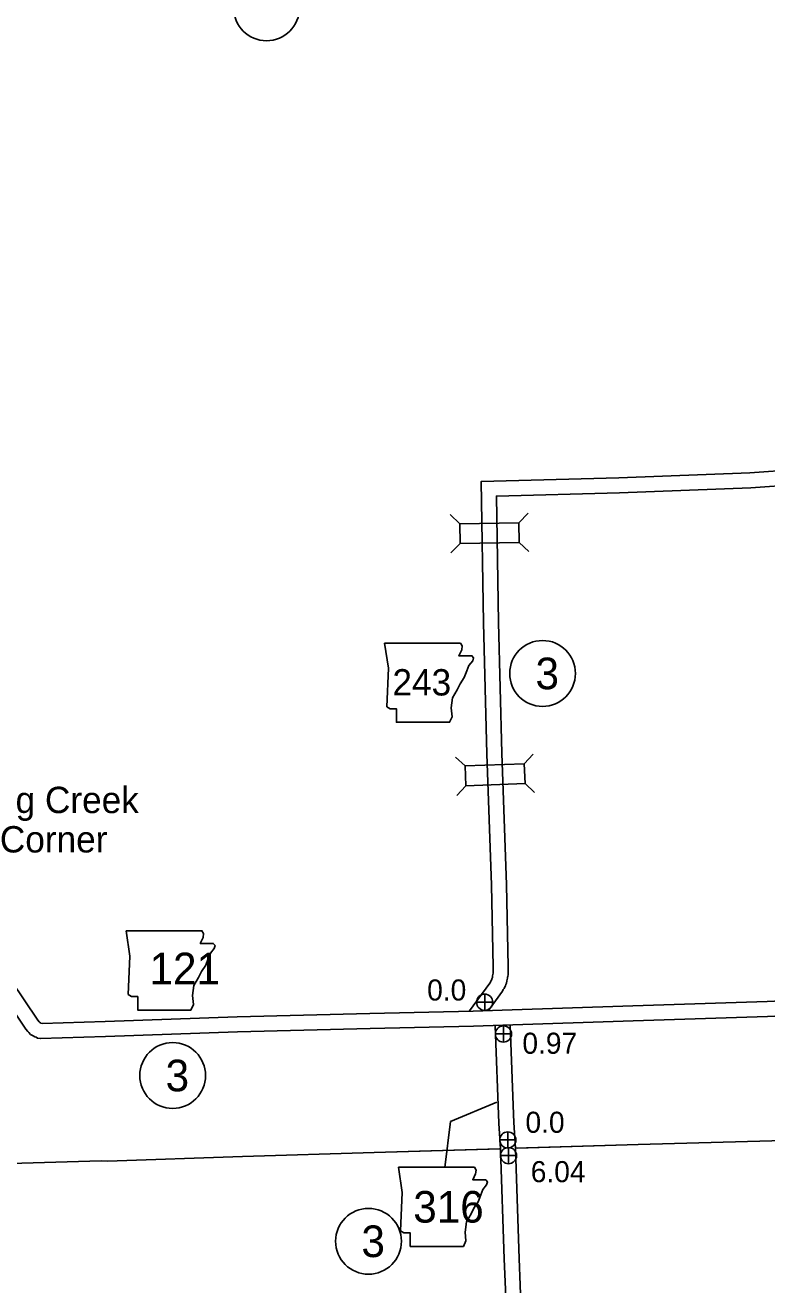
# Model space of a CAD drawing. Extents: x -939622 to -934222, y 1383701 to 1385301.
# Drawn here: x -935826.6 to -935782, y 1384106.1 to 1384181.9 of the extents above; entities that cross this region are included whole.
import ezdxf

# ---------------------------------------------------------------- set-up
doc = ezdxf.new("R2010")
doc.units = 0
for name, color, linetype in [('Level 10', 7, 'Continuous'), ('Level 2', 7, 'Continuous'), ('Level 20', 7, 'Continuous'), ('Level 21', 7, 'Continuous'), ('Level 24', 7, 'Continuous'), ('Level 25', 7, 'Continuous'), ('Level 26', 7, 'Continuous'), ('Level 27', 7, 'Continuous')]:
    doc.layers.add(name, color=color, linetype=linetype)

msp = doc.modelspace()

# ---------------------------------------------------------------- linework, layer by layer
at = {"layer": 'Level 10'}
for points in [[(-935799.877, 1384122.563), (-935798.668, 1384124.24), (-935798.613, 1384124.338), (-935798.595, 1384124.364), (-935798.581, 1384124.395), (-935798.553, 1384124.45), (-935798.536, 1384124.494), (-935798.519, 1384124.533), (-935798.508, 1384124.576), (-935798.502, 1384124.606), (-935798.494, 1384124.669), (-935798.476, 1384124.765), (-935798.462, 1384124.837), (-935798.456, 1384124.863), (-935798.454, 1384124.93), (-935798.464, 1384125.208), (-935798.565, 1384130.123), (-935798.844, 1384138.033), (-935799.044, 1384145.919), (-935799.186, 1384154.404), (-935790.894, 1384154.638), (-935783.01, 1384154.93), (-935780.19, 1384155.135)], [(-935798.743, 1384122.596), (-935797.908, 1384123.755), (-935797.852, 1384123.855), (-935797.809, 1384123.916), (-935797.768, 1384124.008), (-935797.73, 1384124.082), (-935797.704, 1384124.148), (-935797.662, 1384124.245), (-935797.632, 1384124.372), (-935797.614, 1384124.452), (-935797.604, 1384124.534), (-935797.592, 1384124.596), (-935797.583, 1384124.645), (-935797.558, 1384124.747), (-935797.554, 1384124.934), (-935797.564, 1384125.233), (-935797.665, 1384130.148), (-935797.944, 1384138.06), (-935798.144, 1384145.938), (-935798.272, 1384153.529), (-935790.865, 1384153.738), (-935782.96, 1384154.031), (-935780.127, 1384154.237)], [(-935821.784, 1384121.022), (-935825.705, 1384120.902), (-935825.873, 1384120.93), (-935825.972, 1384120.985), (-935826.049, 1384121.013), (-935826.145, 1384121.064), (-935826.185, 1384121.088), (-935826.306, 1384121.152), (-935826.408, 1384121.264), (-935826.468, 1384121.335), (-935826.574, 1384121.466), (-935828.264, 1384123.968)], [(-935821.811, 1384121.922), (-935825.597, 1384121.806), (-935825.681, 1384121.837), (-935825.706, 1384121.85), (-935825.743, 1384121.872), (-935825.774, 1384121.909), (-935825.852, 1384122.004), (-935827.466, 1384124.394)], [(-935774.547, 1384123.471), (-935781.984, 1384123.139), (-935790.06, 1384122.874), (-935797.92, 1384122.61), (-935799.671, 1384122.547), (-935805.892, 1384122.401), (-935813.871, 1384122.204), (-935821.814, 1384121.921)], [(-935774.516, 1384122.572), (-935781.949, 1384122.24), (-935790.03, 1384121.975), (-935797.889, 1384121.711), (-935799.644, 1384121.648), (-935805.87, 1384121.502), (-935813.844, 1384121.305), (-935821.781, 1384121.022)], [(-935798.337, 1384121.678), (-935798.121, 1384115.811)], [(-935797.438, 1384121.712), (-935797.222, 1384115.844)], [(-935798.12, 1384115.797), (-935798.018, 1384114.276)], [(-935797.222, 1384115.858), (-935797.118, 1384114.304)], [(-935798.016, 1384114.251), (-935798.015, 1384114.226), (-935797.797, 1384107.646), (-935797.669, 1384104.428)], [(-935797.116, 1384114.281), (-935797.116, 1384114.271), (-935796.897, 1384107.678), (-935796.77, 1384104.464)]]:
    msp.add_lwpolyline(points, dxfattribs=at)
at = {"layer": 'Level 2'}
for points in [[(-935797.118, 1384114.304), (-935789.737, 1384114.523), (-935781.692, 1384114.748), (-935774.237, 1384115.052)], [(-935797.024, 1384114.306), (-935789.737, 1384114.523), (-935781.692, 1384114.748), (-935774.341, 1384115.048)], [(-935822.047, 1384113.558), (-935821.668, 1384113.537), (-935813.549, 1384113.816), (-935805.624, 1384114.04), (-935798.018, 1384114.276)], [(-935822.047, 1384113.558), (-935821.668, 1384113.537), (-935813.549, 1384113.816), (-935805.624, 1384114.04), (-935798.107, 1384114.274)], [(-935833.528, 1384113.191), (-935829.685, 1384113.314), (-935829.574, 1384113.326), (-935822.047, 1384113.558)], [(-935833.35, 1384113.197), (-935829.685, 1384113.314), (-935829.574, 1384113.326), (-935822.047, 1384113.558)]]:
    msp.add_lwpolyline(points, dxfattribs=at)
at = {"layer": 'Level 20'}
for p, q in [((-935800.476, 1384151.874), (-935801.046, 1384152.425)), ((-935796.913, 1384151.934), (-935796.362, 1384152.504)), ((-935800.456, 1384150.687), (-935801.007, 1384150.117)), ((-935796.893, 1384150.746), (-935796.323, 1384150.196)), ((-935800.152, 1384137.299), (-935800.732, 1384137.838)), ((-935796.59, 1384137.432), (-935796.052, 1384138.012)), ((-935800.108, 1384136.112), (-935800.647, 1384135.531)), ((-935796.546, 1384136.245), (-935795.966, 1384135.706))]:
    msp.add_line(p, q, dxfattribs=at)
for points in [[(-935800.456, 1384150.687), (-935796.893, 1384150.746), (-935796.913, 1384151.934), (-935800.476, 1384151.874)], [(-935800.108, 1384136.112), (-935796.546, 1384136.245), (-935796.59, 1384137.432), (-935800.152, 1384137.299)]]:
    msp.add_lwpolyline(points, close=True, dxfattribs=at)
at = {"layer": 'Level 21'}
for p, q in [((-935798.233, 1384117.08), (-935801.024, 1384115.921)), ((-935801.024, 1384115.921), (-935801.377, 1384113.146))]:
    msp.add_line(p, q, dxfattribs=at)
for points in [[(-935804.995, 1384144.695), (-935804.767, 1384143.173), (-935804.868, 1384140.864), (-935804.665, 1384140.737), (-935804.284, 1384140.737), (-935804.284, 1384139.925), (-935801.087, 1384139.925), (-935800.935, 1384140.255), (-935800.985, 1384140.787), (-935800.909, 1384141.396), (-935800.63, 1384141.879), (-935800.453, 1384142.234), (-935800.199, 1384142.615), (-935800.046, 1384143.021), (-935799.92, 1384143.35), (-935799.691, 1384143.63), (-935799.64, 1384143.807), (-935799.742, 1384143.934), (-935800.529, 1384143.934), (-935800.351, 1384144.289), (-935800.326, 1384144.518), (-935800.431, 1384144.693)], [(-935820.556, 1384127.392), (-935820.327, 1384125.869), (-935820.429, 1384123.56), (-935820.226, 1384123.433), (-935819.845, 1384123.433), (-935819.845, 1384122.621), (-935816.648, 1384122.621), (-935816.495, 1384122.951), (-935816.546, 1384123.484), (-935816.47, 1384124.093), (-935816.191, 1384124.575), (-935816.013, 1384124.93), (-935815.76, 1384125.311), (-935815.607, 1384125.717), (-935815.48, 1384126.047), (-935815.252, 1384126.326), (-935815.201, 1384126.503), (-935815.303, 1384126.63), (-935816.089, 1384126.63), (-935815.912, 1384126.986), (-935815.886, 1384127.214), (-935815.992, 1384127.389)], [(-935804.16, 1384113.17), (-935803.931, 1384111.648), (-935804.033, 1384109.338), (-935803.83, 1384109.211), (-935803.449, 1384109.211), (-935803.449, 1384108.399), (-935800.252, 1384108.399), (-935800.099, 1384108.729), (-935800.15, 1384109.262), (-935800.074, 1384109.871), (-935799.795, 1384110.353), (-935799.617, 1384110.709), (-935799.363, 1384111.089), (-935799.211, 1384111.495), (-935799.084, 1384111.825), (-935798.856, 1384112.104), (-935798.805, 1384112.282), (-935798.907, 1384112.409), (-935799.693, 1384112.409), (-935799.516, 1384112.764), (-935799.49, 1384112.993), (-935799.596, 1384113.168)]]:
    msp.add_lwpolyline(points, close=True, dxfattribs=at)
at = {"layer": 'Level 26'}
for p, q in [((-935798.974, 1384122.599), (-935798.974, 1384123.574)), ((-935799.462, 1384123.087), (-935798.487, 1384123.087)), ((-935797.845, 1384120.69), (-935797.845, 1384121.665)), ((-935798.332, 1384121.178), (-935797.357, 1384121.178)), ((-935797.582, 1384114.318), (-935797.582, 1384115.293)), ((-935798.069, 1384114.805), (-935797.094, 1384114.805)), ((-935797.541, 1384113.375), (-935797.541, 1384114.35)), ((-935798.029, 1384113.863), (-935797.054, 1384113.863))]:
    msp.add_line(p, q, dxfattribs=at)
for centre in [(-935798.974, 1384123.087), (-935797.845, 1384121.178), (-935797.582, 1384114.805), (-935797.541, 1384113.863)]:
    msp.add_circle(centre, 0.487, dxfattribs=at)
at = {"layer": 'Level 27'}
for centre in [(-935812.097, 1384182.902), (-935795.49, 1384142.866), (-935817.748, 1384118.68), (-935805.965, 1384108.709)]:
    msp.add_circle(centre, 1.98, dxfattribs=at)

# ---------------------------------------------------------------- texts
at = {"layer": 'Level 21'}
for s, height, p in [('243', 1.584, (-935804.525, 1384141.539)), ('121', 1.9008, (-935819.14, 1384124.169)), ('316', 1.9008, (-935803.272, 1384109.833))]:
    msp.add_text(s, height=height, dxfattribs=at).set_placement(p)
at = {"layer": 'Level 24'}
for s, p in [('Big Creek', (-935829.083, 1384134.465)), ('Corner', (-935828.147, 1384132.096))]:
    msp.add_text(s, height=1.584, dxfattribs=at).set_placement(p)
at = {"layer": 'Level 25'}
for s, p in [('0.0', (-935802.435, 1384123.191)), ('0.97', (-935796.705, 1384119.989)), ('0.0', (-935796.52, 1384115.235)), ('6.04', (-935796.202, 1384112.264))]:
    msp.add_text(s, height=1.2672, dxfattribs=at).set_placement(p)
at = {"layer": 'Level 27'}
for p in [(-935795.915, 1384141.916), (-935818.173, 1384117.73), (-935806.39, 1384107.759)]:
    msp.add_text('3', height=1.901, dxfattribs=at).set_placement(p)

doc.saveas('drawing.dxf')
